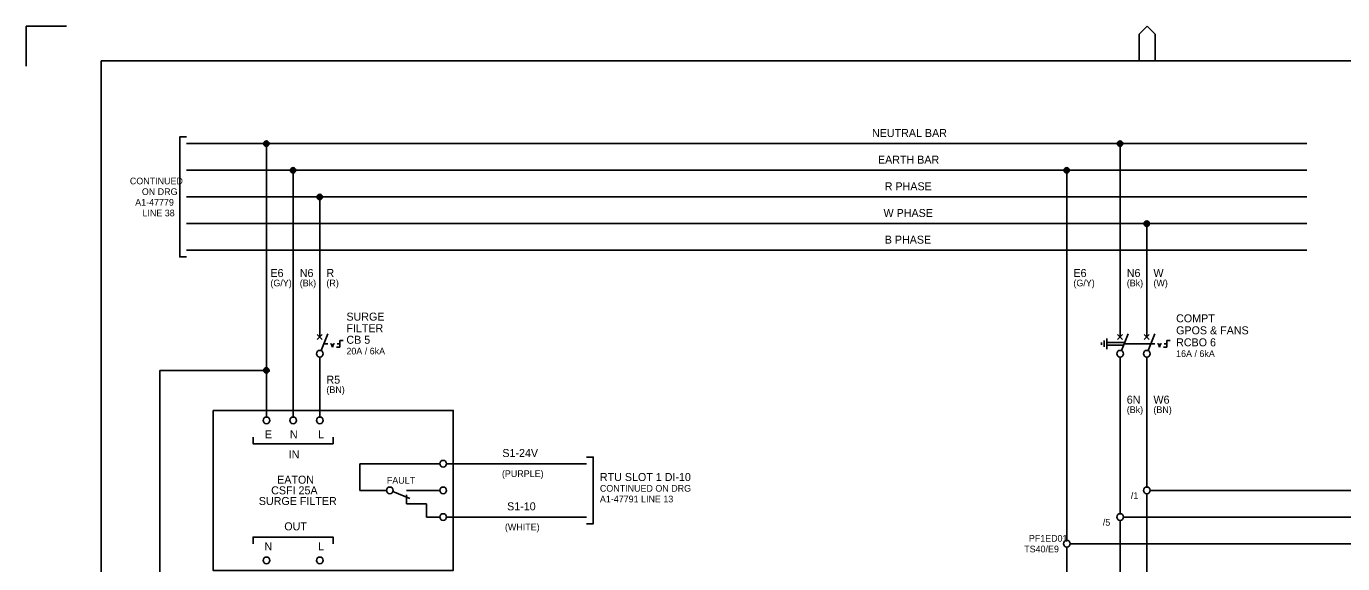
# Model space of a CAD drawing. Extents: x 0 to 841, y 0 to 594.
# Drawn here: x 0 to 493.4, y 392.5 to 594 of the extents above; entities that cross this region are included whole.
import ezdxf

# ---------------------------------------------------------------- set-up
doc = ezdxf.new("R2010")
doc.units = 0
for name, color, linetype in [('A1BORDER', 7, 'Continuous'), ('Level 1', 7, 'Continuous'), ('Level 10', 7, 'Continuous')]:
    doc.layers.add(name, color=color, linetype=linetype)

msp = doc.modelspace()

# ---------------------------------------------------------------- linework, layer by layer
at = {"layer": 'A1BORDER'}
for p, q in [((0, 594), (15, 594)), ((0, 579), (0, 594)), ((417.19, 591), (420.19, 594)), ((423.19, 591), (420.19, 594)), ((417.19, 581), (417.19, 591)), ((423.19, 581), (423.19, 591)), ((28, 581), (829, 581)), ((28, 581), (28, 15))]:
    msp.add_line(p, q, dxfattribs=at)
at = {"layer": 'Level 1'}
for p, q in [((60, 550), (480, 550)), ((90, 550), (90, 447.5)), ((410, 550), (410, 480)), ((60, 540), (480, 540)), ((100, 540), (100, 447.5)), ((390, 401.25), (390, 540)), ((480, 530), (60, 530)), ((110, 530), (110, 480)), ((60, 520), (480, 520)), ((420, 520), (420, 480)), ((60, 510), (480, 510)), ((110, 477.5), (110, 480)), ((110, 477.5), (110, 480)), ((110.46, 472.41), (113, 478.75)), ((110.46, 472.41), (113, 478.75)), ((410, 477.5), (410, 480)), ((410.46, 472.41), (413, 478.75)), ((420, 477.5), (420, 480)), ((420.46, 472.41), (423, 478.75)), ((109.06, 478.44), (110.94, 476.56)), ((110.94, 478.44), (109.06, 476.56)), ((109.06, 478.44), (110.94, 476.56)), ((110.94, 478.44), (109.06, 476.56)), ((405, 475.5), (411.7, 475.5)), ((405, 474.5), (411.3, 474.5)), ((409.06, 478.44), (410.94, 476.56)), ((410.94, 478.44), (409.06, 476.56)), ((411.5, 475), (421.5, 475)), ((419.06, 478.44), (420.94, 476.56)), ((420.94, 478.44), (419.06, 476.56)), ((110, 470), (110, 447.5)), ((410, 470), (410, 411.25)), ((420, 470), (420, 421.25)), ((90, 465), (50, 465)), ((50, 465), (50, 375)), ((90, 447.5), (90, 447.5)), ((90, 445), (90, 445)), ((100, 447.5), (100, 447.5)), ((100, 445), (100, 445)), ((110, 447.5), (110, 447.5)), ((110, 445), (110, 445)), ((125, 420), (125, 430)), ((125, 430), (155, 430)), ((156.25, 431.25), (156.25, 431.25)), ((210, 430), (157.5, 430)), ((156.25, 428.75), (156.25, 428.75)), ((135, 420), (125, 420)), ((145, 420), (155, 420)), ((156.25, 421.25), (156.25, 421.25)), ((421.25, 420), (538.75, 420)), ((145, 415), (150, 415)), ((150, 410), (150, 415)), ((156.25, 418.75), (156.25, 418.75)), ((419.98, 200), (419.98, 418.75)), ((150, 410), (155, 410)), ((156.25, 411.25), (156.25, 411.25)), ((210, 410), (157.5, 410)), ((411.25, 410), (528.75, 410)), ((156.25, 408.75), (156.25, 408.75)), ((410, 408.75), (410, 180)), ((391.25, 400), (518.75, 400)), ((90, 395), (90, 395)), ((110, 395), (110, 395)), ((390, 160), (390, 398.75))]:
    msp.add_line(p, q, dxfattribs=at)
for points in [[(60, 552.5), (57.5, 552.5), (57.5, 507.5), (60, 507.5)], [(85, 440), (85, 437.5), (115, 437.5), (115, 440)], [(210, 432.5), (212.5, 432.5), (212.5, 407.5), (210, 407.5)], [(85, 400), (85, 402.5), (115, 402.5), (115, 400)]]:
    msp.add_lwpolyline(points, dxfattribs=at)
msp.add_lwpolyline([(70, 450), (160, 450), (160, 390), (70, 390)], close=True, dxfattribs=at)
for centre in [(110, 471.25), (110, 471.25), (410, 471.25), (420, 471.25), (420, 420), (410, 410), (390, 400)]:
    msp.add_circle(centre, 1.25, dxfattribs=at)
at = {"layer": 'Level 10'}
for p, q in [((89.01, 550.1), (90.99, 550.1)), ((89.02, 549.8), (90.98, 549.8)), ((89.08, 550.4), (90.92, 550.4)), ((89.13, 549.5), (90.87, 549.5)), ((89.29, 550.7), (90.71, 550.7)), ((89.4, 549.2), (90.6, 549.2)), ((90, 551), (90, 551)), ((409.01, 550.1), (410.99, 550.1)), ((409.02, 549.8), (410.98, 549.8)), ((409.08, 550.4), (410.92, 550.4)), ((409.13, 549.5), (410.87, 549.5)), ((409.29, 550.7), (410.71, 550.7)), ((409.4, 549.2), (410.6, 549.2)), ((410, 551), (410, 551)), ((99.01, 540.1), (100.99, 540.1)), ((99.02, 539.8), (100.98, 539.8)), ((99.08, 540.4), (100.92, 540.4)), ((99.13, 539.5), (100.87, 539.5)), ((99.29, 540.7), (100.71, 540.7)), ((99.4, 539.2), (100.6, 539.2)), ((100, 541), (100, 541)), ((389.01, 540.1), (390.99, 540.1)), ((389.02, 539.8), (390.98, 539.8)), ((389.08, 540.4), (390.92, 540.4)), ((389.13, 539.5), (390.87, 539.5)), ((389.29, 540.7), (390.71, 540.7)), ((389.4, 539.2), (390.6, 539.2)), ((390, 541), (390, 541)), ((109.01, 530.1), (110.99, 530.1)), ((109.02, 529.8), (110.98, 529.8)), ((109.08, 530.4), (110.92, 530.4)), ((109.13, 529.5), (110.87, 529.5)), ((109.29, 530.7), (110.71, 530.7)), ((109.4, 529.2), (110.6, 529.2)), ((110, 531), (110, 531)), ((419.01, 520.1), (420.99, 520.1)), ((419.02, 519.8), (420.98, 519.8)), ((419.08, 520.4), (420.92, 520.4)), ((419.13, 519.5), (420.87, 519.5)), ((419.29, 520.7), (420.71, 520.7)), ((419.4, 519.2), (420.6, 519.2)), ((420, 521), (420, 521)), ((111.5, 475), (113, 475)), ((111.5, 475), (113, 475)), ((114, 475), (114.33, 475)), ((114, 475), (114.33, 475)), ((114.75, 473.75), (114.33, 475)), ((114.75, 473.75), (114.33, 475)), ((114.75, 473.75), (115.17, 475)), ((114.75, 473.75), (115.17, 475)), ((115.5, 475), (115.17, 475)), ((115.5, 475), (115.17, 475)), ((116.25, 473.75), (117.5, 473.75)), ((116.25, 473.75), (117.5, 473.75)), ((116.5, 475), (117.5, 475)), ((116.5, 475), (117.5, 475)), ((117.5, 473.75), (117.5, 476.25)), ((117.5, 476.25), (118.75, 476.25)), ((117.5, 473.75), (117.5, 476.25)), ((117.5, 476.25), (118.75, 476.25)), ((403, 475.4), (403, 474.6)), ((404, 476.2), (404, 473.8)), ((405, 477), (405, 473)), ((421.5, 475), (423, 475)), ((424, 475), (424.33, 475)), ((424.75, 473.75), (424.33, 475)), ((424.75, 473.75), (425.17, 475)), ((425.5, 475), (425.17, 475)), ((426.25, 473.75), (427.5, 473.75)), ((426.5, 475), (427.5, 475)), ((427.5, 473.75), (427.5, 476.25)), ((427.5, 476.25), (428.75, 476.25)), ((89, 465), (90.99, 465)), ((89.05, 465.3), (90.95, 465.3)), ((89.05, 464.7), (90.95, 464.7)), ((89.2, 465.6), (90.8, 465.6)), ((89.2, 464.4), (90.8, 464.4)), ((89.56, 465.9), (90.44, 465.9)), ((89.56, 464.1), (90.44, 464.1)), ((90, 466), (90, 466)), ((137.41, 419.54), (143.75, 417)), ((142.5, 420), (145, 420)), ((142.5, 418.37), (142.5, 415)), ((142.5, 415), (145, 415))]:
    msp.add_line(p, q, dxfattribs=at)
for centre, radius in [((90, 550), 1), ((410, 550), 1), ((100, 540), 1), ((390, 540), 1), ((110, 530), 1), ((420, 520), 1), ((90, 465), 1), ((90, 446.25), 1.25), ((100, 446.25), 1.25), ((110, 446.25), 1.25), ((156.25, 430), 1.25), ((136.25, 420), 1.25), ((156.25, 420), 1.25), ((156.25, 410), 1.25), ((90, 393.75), 1.25), ((110, 393.75), 1.25)]:
    msp.add_circle(centre, radius, dxfattribs=at)

# ---------------------------------------------------------------- texts
at = {"layer": 'Level 1'}
for s, height, p in [('NEUTRAL BAR', 3, (317, 552.5)), ('EARTH BAR', 3, (319.24, 542.5)), ('CONTINUED', 2.5, (38.81, 534.75)), ('ON DRG', 2.5, (43.3, 530.75)), ('R PHASE', 3, (321.78, 532.5)), ('A1-47779', 2.5, (40.81, 526.75)), ('LINE 38', 2.5, (43.54, 522.75)), ('W PHASE', 3, (321.33, 522.5)), ('B PHASE', 3, (321.78, 512.5)), ('(G/Y)', 2.5, (91.5, 496.5)), ('E6', 3, (91.5, 500)), ('(Bk)', 2.5, (102.5, 496.5)), ('N6', 3, (102.5, 500)), ('(R)', 2.5, (112.5, 496.5)), ('R', 3, (112.5, 500)), ('(G/Y)', 2.5, (392.5, 496.5)), ('E6', 3, (392.5, 500)), ('(Bk)', 2.5, (412.5, 496.5)), ('N6', 3, (412.5, 500)), ('W', 3, (422.5, 500)), ('(W)', 2.5, (422.5, 496.5)), ('SURGE', 3, (119.98, 483.64)), ('SURGE', 3, (119.98, 483.64)), ('COMPT', 3, (431, 483)), ('FILTER', 3, (119.98, 479.3)), ('FILTER', 3, (119.98, 479.3)), ('GPOS & FANS', 3, (431, 478.5)), ('CB 5', 3, (119.98, 474.96)), ('CB 5', 3, (119.98, 474.96)), ('RCBO 6', 3, (431, 474)), ('20A / 6kA', 2.5, (119.98, 470.96)), ('20A / 6kA', 2.5, (119.98, 470.96)), ('16A / 6kA', 2.5, (431, 470)), ('(BN)', 2.5, (112.5, 456.5)), ('R5', 3, (112.5, 460)), ('6N', 3, (412.5, 452.5)), ('W6', 3, (422.5, 452.5)), ('(Bk)', 2.5, (412.5, 449)), ('(BN)', 2.5, (422.5, 449)), ('E', 3, (89.4, 439.5)), ('N', 3, (98.8, 439.5)), ('L', 3, (109.4, 439.5)), ('IN', 3, (98.35, 432)), ('S1-24V', 3, (178.43, 432.5)), ('EATON', 3, (94.02, 422.5)), ('FAULT', 2.5, (135.14, 422.5)), ('(PURPLE)', 2.5, (178.28, 425)), ('RTU SLOT 1 DI-10', 3, (215, 423.5)), ('CSFI 25A', 3, (91.78, 418.5)), ('CONTINUED ON DRG', 2.5, (215, 419.5)), ('SURGE FILTER', 3, (87.15, 414.5)), ('S1-10', 3, (180.22, 412.5)), ('A1-47791 LINE 13', 2.5, (215, 415.5)), ('/1', 2.5, (414.02, 416.74)), ('OUT', 3, (96.7, 405)), ('(WHITE)', 2.5, (179.4, 405)), ('/5', 2.5, (403.52, 406.74)), ('N', 3, (89.26, 397.5)), ('L', 3, (109.4, 397.5)), ('PF1ED01', 2.5, (375.8, 400.74)), ('TS40/E9', 2.5, (374.06, 396.74))]:
    msp.add_text(s, height=height, dxfattribs=at).set_placement(p)

doc.saveas('drawing.dxf')
